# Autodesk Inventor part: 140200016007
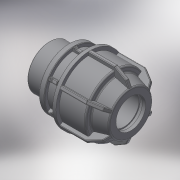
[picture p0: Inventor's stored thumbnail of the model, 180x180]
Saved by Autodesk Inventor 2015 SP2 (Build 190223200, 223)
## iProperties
Created: 2017-08
Part Number: 140200016007
Material: Generic
Description: PLASSON L.14 MALE ADAPTOR (SILVER) 16-3/4''
Document SubType Name: Modeling
Designer: KIM
Density: 1 g/cm^3
Appearance: Default
Author: KIM
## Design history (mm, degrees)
derived "140200.ipt"
feature "Solid1::140200.ipt"
tag "TaggingFeature1"
body "Solid1"
other parameters: "d1" = 16, "d2" = 59, "d4" = 15 deg, "d5" = 38.94, "d6" = 12.8502, "d10" = 39, "d16" = 16.32, "d17" = 2.95, "d19" = 5.1, "d21" = 5.1, "d22" = 31.7292, "d24" = 2.95, "d25" = 35.1, "d26" = 29.25, "d27" = 2.95, "d28" = 135 deg, "d29" = 1.77, "d31" = 0.8, "d44" = 0.32, "d45" = 0.48, "d46" = 150 deg, "d49" = 1.95, "d50" = 0, "d51" = 1.17, "d52" = 0.78, "d53" = 45 deg, "d54" = 21, "d55" = 8.4, "d56" = 1.95, "d57" = 0, "d58" = 0.48, "d59" = 0.32, "d61" = 360 deg, "d63" = 26.441, "d64" = 12.8, "d65" = 17, "d66" = 35.69535, "d_" = 16, "R_" = 26.441, "E_" = 39, "l_" = 59, "l_2" = 17
